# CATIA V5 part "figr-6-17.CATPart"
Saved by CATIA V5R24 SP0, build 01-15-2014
Part number: Part1
Bounding box of the stored display mesh (mm): x 0 to 150, y -70 to 70, z -150 to 69.804
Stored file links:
  D:\KAVITA\CATIA V5-6R2014 Project_ Kavita\CATIA V5-6R2014_partfiles\Partfiles\c06_catia_v5-6r2014_prt\figr-6-17.CATPart
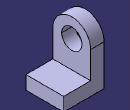
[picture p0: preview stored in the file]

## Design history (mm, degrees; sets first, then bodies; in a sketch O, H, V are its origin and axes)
Body1 (main body)
  Sketch1 on yz-plane, origin (0, 0, 0), H (0, 1, 0), V (0, 0, 1)
    arc A1 centre (0, 0) radius 70 from (70, 0) to (-70, 0) ccw
    point P1 (70, 0)
    point P2 (-70, 0)
    line L1 (-70, 0) -> (-70, -150)
    line L2 (-70, -150) -> (70, -150)
    line L3 (70, -150) -> (70, 0)
    circle A2 centre (0, 0) radius 37.5
    radius A1 = 70
    radius A2 = 37.5
    distance O L2 = 150
    coincidence: P1 H, P2 H
    tangency: L1 A1, L3 A1
    horizontal: L2 H
  Pad1: profile Sketch1, direction (1, 0, 0), length 50
  Sketch2 on face of Pad1, origin (50, 0, 0), H (0, 1, 0), V (0, 0, 1)
    line L1 (-70, -150) -> (70, -150)
    line L2 (70, -150) -> (70, -100)
    line L3 (70, -100) -> (-70, -100)
    line L4 (-70, -100) -> (-70, -150)
    reference projected line E1 (-70, -150) -> (70, -150) from edge [face of Pad1 | face of Pad1]
    reference projected line E2 (-70, 0) -> (-70, -150) from edge [face of Pad1 | face of Pad1]
    reference projected line E3 (70, -150) -> (70, 0) from edge [face of Pad1 | face of Pad1]
    length L2 = 50
    horizontal: L1 H, L3 H
    vertical: L2 V, L4 V
    coincidence: L1 E1, E2 L4, L2 E3
  Pad2: profile Sketch2, direction (1, 0, 0), length 100
  Sketch3 on face of Pad1, origin (50, 0, 0), H (0, 1, 0), V (0, 0, 1)
    point P1 (45.5554, 53.148)
    reference projected arc E1 centre (0, 0) radius 70 from (70, 0) to (-70, 0) ccw from edge [face of Pad1 | face of Pad1]
    coincidence: P1 E1
  Sketch4 on face of Pad2, origin (0, 0, -100), H (1, 0, 0), V (0, 1, 0)
    point P1 (110, 20)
